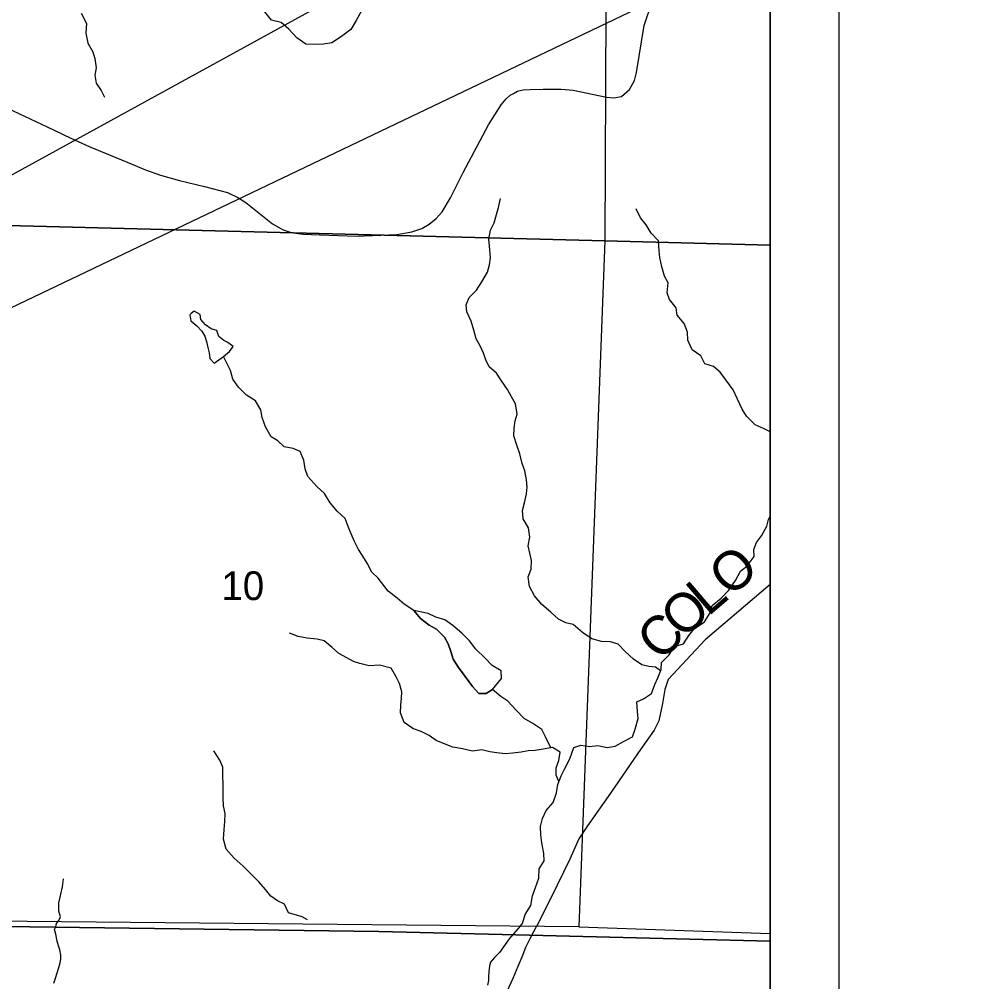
# Model space of a CAD drawing. Extents: x 0 to 34, y 0 to 22.
# Drawn here: x 7.806 to 9.2, y 17.833 to 19.235 of the extents above; entities that cross this region are included whole.
import ezdxf

# ---------------------------------------------------------------- set-up
doc = ezdxf.new("R2010")
doc.units = 0
for name, color, linetype in [('Default', 7, 'Continuous'), ('GM_X_Corporation', 7, 'Continuous'), ('GM_X_County_Road_Text', 7, 'Continuous'), ('GM_X_Interchange_Ramps', 7, 'Continuous'), ('GM_X_Interstate_Route', 7, 'Continuous'), ('GM_X_Major_Lake', 7, 'Continuous'), ('GM_X_Minor_Lake', 7, 'Continuous'), ('GM_X_Minor_River', 7, 'Continuous'), ('GM_X_Township_Road_Text', 7, 'Continuous'), ('SH_Cut_Line', 7, 'Continuous'), ('SH_Data', 7, 'Continuous')]:
    doc.layers.add(name, color=color, linetype=linetype)

msp = doc.modelspace()

# ---------------------------------------------------------------- linework, layer by layer
at = {"layer": 'Default'}
for points in [[(8.9, 18.9055), (8.9, 19.9241), (8.6637, 19.9273), (8.659, 18.9119)], [(8.9, 17.9031), (8.9, 18.9055), (8.659, 18.9119), (8.6215, 17.9129)]]:
    msp.add_lwpolyline(points, close=True, dxfattribs=at)
at = {"layer": 'GM_X_Corporation'}
msp.add_lwpolyline([(8.9, 18.4116), (8.8053, 18.3308), (8.7515, 18.2731), (8.7468, 18.2586), (8.7431, 18.2383), (8.7376, 18.213), (8.7312, 18.1991), (8.7079, 18.166), (8.6673, 18.1074), (8.6339, 18.0598), (8.6215, 18.0409), (8.6083, 18.0114), (8.5807, 17.9546), (8.5594, 17.9133)], dxfattribs=at)
at = {"layer": 'GM_X_Interchange_Ramps'}
for points in [[(8.9, 17.8921), (8.9, 20.9), (6.6698, 20.9), (6.6438, 19.9593), (6.6304, 19.2166), (6.6258, 18.9603), (6.6079, 18.3189), (6.5943, 17.9356), (7.6027, 17.9156), (8.3297, 17.9059), (8.5492, 17.9006)], [(6.5113, 14.1), (8.9, 14.1), (8.9, 17.8921), (8.5492, 17.9006), (8.3297, 17.9059), (7.6027, 17.9156), (6.5943, 17.9356), (6.5883, 17.471), (6.5647, 16.5359), (6.5572, 16.1864), (6.5411, 15.4243), (6.5389, 15.3228)]]:
    msp.add_lwpolyline(points, close=True, dxfattribs=at)
msp.add_lwpolyline([(7.7718, 19.1131), (7.8466, 19.0782), (7.8814, 19.0615), (7.9081, 19.0494), (7.963, 19.0266), (7.99, 19.0156), (8.0118, 19.0077), (8.0396, 18.9999), (8.076, 18.9911), (8.1095, 18.9822), (8.1245, 18.9749), (8.1359, 18.9679), (8.1749, 18.9366), (8.1905, 18.9279), (8.202, 18.924), (8.2199, 18.9219), (8.2441, 18.9208), (8.2976, 18.919), (8.3562, 18.921), (8.3781, 18.925), (8.3926, 18.9297), (8.4034, 18.9364), (8.4134, 18.9446), (8.4223, 18.9542), (8.4341, 18.9745), (8.4529, 19.0115), (8.4897, 19.0808), (8.5081, 19.1101), (8.5154, 19.1188), (8.5212, 19.1242), (8.526, 19.1268), (8.532, 19.1298), (8.54, 19.1321), (8.5506, 19.1326), (8.5694, 19.1328), (8.5954, 19.1331), (8.613, 19.1312), (8.6615, 19.1212), (8.6722, 19.1202), (8.6833, 19.1223), (8.6949, 19.1325), (8.7025, 19.1454), (8.7051, 19.157), (8.7167, 19.2254), (8.7288, 19.2617)], dxfattribs=at)
at = {"layer": 'GM_X_Interstate_Route'}
msp.add_lwpolyline([(8.517, 17.8189), (8.5254, 17.8382), (8.5331, 17.8557), (8.5385, 17.8692), (8.5442, 17.883), (8.5503, 17.8957), (8.5556, 17.9062), (8.5594, 17.9133)], dxfattribs=at)
at = {"layer": 'GM_X_Minor_Lake'}
for points in [[(7.6626, 19.9442), (8.6637, 19.9273), (8.659, 18.9119), (7.637, 18.9382)], [(7.637, 18.9382), (8.659, 18.9119), (8.6215, 17.9129), (7.6162, 17.9223)]]:
    msp.add_lwpolyline(points, close=True, dxfattribs=at)
at = {"layer": 'GM_X_Minor_River'}
for points in [[(8.0567, 18.8063), (8.0543, 18.8044), (8.0562, 18.7956), (8.0646, 18.7881), (8.0719, 18.7806), (8.0765, 18.773), (8.0789, 18.7651), (8.0809, 18.7567), (8.0828, 18.7488), (8.0836, 18.7404), (8.0898, 18.734), (8.1034, 18.7437)], [(8.1034, 18.7437), (8.1121, 18.7509), (8.1177, 18.7582), (8.1097, 18.7638), (8.1039, 18.7668), (8.0967, 18.7728), (8.0939, 18.7815), (8.0856, 18.7837), (8.0775, 18.7898), (8.0706, 18.7973), (8.0694, 18.8049), (8.0607, 18.8093), (8.0567, 18.8063)], [(8.3811, 18.3733), (8.3907, 18.362), (8.4034, 18.3524), (8.4137, 18.3461), (8.4257, 18.3346), (8.4307, 18.3248), (8.4347, 18.3138), (8.4383, 18.3025), (8.4461, 18.2905), (8.4557, 18.2774), (8.4662, 18.2628), (8.4758, 18.2527), (8.4864, 18.2525), (8.4955, 18.2583)], [(8.4955, 18.2583), (8.5088, 18.2745), (8.5082, 18.2855), (8.4952, 18.2936), (8.4841, 18.3048), (8.4714, 18.3171), (8.4621, 18.3295), (8.4509, 18.3403), (8.4375, 18.3518), (8.426, 18.36), (8.413, 18.3639), (8.4016, 18.3691), (8.3811, 18.3733)]]:
    msp.add_lwpolyline(points, dxfattribs=at)
at = {"layer": 'GM_X_Township_Road_Text'}
for points in [[(8.3164, 19.2599), (8.3046, 19.2469), (8.2968, 19.2331), (8.2889, 19.2198), (8.2757, 19.2094), (8.2613, 19.2002), (8.2492, 19.1982), (8.2367, 19.1977), (8.2234, 19.1983), (8.2104, 19.2077), (8.1989, 19.2201), (8.1878, 19.2299), (8.1733, 19.2332), (8.1637, 19.2453), (8.1545, 19.2573), (8.1487, 19.2725), (8.1474, 19.2857), (8.1431, 19.2993), (8.1339, 19.3107)], [(7.8963, 19.2437), (7.9041, 19.2286), (7.903, 19.2142), (7.9058, 19.1998), (7.9131, 19.1873), (7.9163, 19.1775), (7.9179, 19.1638), (7.9161, 19.1535), (7.9181, 19.1414), (7.9254, 19.1309), (7.93, 19.121)], [(8.7404, 18.2858), (8.733, 18.2912), (8.7235, 18.2918), (8.7132, 18.2943), (8.701, 18.3025), (8.6887, 18.3136), (8.6787, 18.3245), (8.6673, 18.3281), (8.6544, 18.3282), (8.6403, 18.3322), (8.6265, 18.3414), (8.6131, 18.3533), (8.6025, 18.3554), (8.5918, 18.3609), (8.5806, 18.371), (8.5672, 18.3821), (8.5568, 18.3949), (8.5493, 18.4084), (8.5476, 18.4224), (8.5519, 18.4339), (8.5525, 18.4464), (8.5476, 18.4676), (8.5497, 18.4805), (8.5479, 18.4938), (8.5401, 18.5069), (8.5392, 18.519), (8.542, 18.5305), (8.5448, 18.5434), (8.5462, 18.5533), (8.5452, 18.5639), (8.5424, 18.5768), (8.5388, 18.5877), (8.5355, 18.6017), (8.5308, 18.6141), (8.5268, 18.6277), (8.527, 18.6391), (8.5287, 18.6498), (8.5315, 18.6593), (8.529, 18.6744), (8.5232, 18.6846), (8.5173, 18.6955), (8.5084, 18.7079), (8.5014, 18.7191), (8.4906, 18.7284), (8.4859, 18.7386), (8.4824, 18.7484), (8.4773, 18.7589), (8.4718, 18.7691), (8.4682, 18.7819), (8.4642, 18.7951), (8.4579, 18.8087), (8.457, 18.8189), (8.4617, 18.8292), (8.4721, 18.84), (8.4802, 18.8523), (8.4883, 18.8661), (8.4912, 18.8768), (8.4925, 18.8878), (8.4911, 18.9041), (8.4902, 18.9143), (8.4926, 18.9273), (8.4981, 18.938), (8.5013, 18.9502), (8.5042, 18.9605), (8.507, 18.9734)], [(8.9, 18.634), (8.8911, 18.6381), (8.8781, 18.644), (8.8658, 18.6567), (8.8592, 18.6668), (8.8525, 18.6811), (8.8462, 18.695), (8.8354, 18.7093), (8.8273, 18.7209), (8.8177, 18.7291), (8.8051, 18.733), (8.7989, 18.7447), (8.7862, 18.7532), (8.7799, 18.7671), (8.7794, 18.7789), (8.7746, 18.7917), (8.7646, 18.8037), (8.7629, 18.8143), (8.7532, 18.8266), (8.75, 18.8364), (8.7513, 18.8509), (8.7462, 18.8607), (8.7422, 18.8742), (8.7393, 18.8875), (8.7384, 18.8973), (8.7374, 18.9121), (8.7266, 18.9229), (8.7192, 18.9353), (8.7111, 18.9454), (8.7048, 18.9586)], [(8.3289, 18.4205), (8.3198, 18.4296), (8.3129, 18.4424), (8.3067, 18.4526), (8.3002, 18.4624), (8.294, 18.4749), (8.2897, 18.4851), (8.2851, 18.4957), (8.2808, 18.5075), (8.2693, 18.5184), (8.259, 18.5304), (8.2509, 18.5437), (8.2398, 18.5542), (8.2264, 18.5689), (8.2225, 18.5799), (8.2208, 18.5924), (8.2154, 18.6053), (8.2051, 18.6097), (8.1922, 18.6119), (8.1826, 18.6205), (8.1731, 18.6265), (8.1646, 18.6409), (8.1599, 18.6545), (8.158, 18.6659), (8.1502, 18.6791), (8.1369, 18.6874), (8.1254, 18.699), (8.1173, 18.7107), (8.1138, 18.7229), (8.1034, 18.7437)], [(8.5358, 17.9136), (8.539, 17.9176), (8.5429, 17.9309), (8.5514, 17.944), (8.5538, 17.958), (8.5581, 17.9703), (8.5632, 17.9836), (8.5637, 17.9973), (8.5707, 18.0088), (8.5702, 18.0194), (8.5676, 18.0353), (8.5659, 18.0467), (8.5654, 18.0588), (8.5682, 18.0706), (8.5737, 18.0821), (8.5841, 18.094), (8.5888, 18.1078), (8.5908, 18.1203), (8.5955, 18.1329), (8.6003, 18.1425), (8.6084, 18.1574), (8.6138, 18.1738), (8.624, 18.1774), (8.6369, 18.1754), (8.6489, 18.1767), (8.6626, 18.1739), (8.6743, 18.176), (8.6871, 18.1834), (8.6995, 18.1897), (8.7034, 18.2008), (8.7077, 18.2164), (8.7068, 18.2263), (8.7058, 18.2403), (8.7156, 18.245), (8.7272, 18.2524), (8.7319, 18.2658), (8.7366, 18.2754), (8.741, 18.2876), (8.7419, 18.2979), (8.7531, 18.309), (8.7605, 18.3209), (8.7737, 18.325), (8.7814, 18.3372), (8.7892, 18.3469), (8.8046, 18.357), (8.8127, 18.37), (8.8155, 18.3807), (8.8286, 18.3915), (8.8397, 18.4031), (8.8494, 18.4173), (8.8567, 18.4307), (8.8664, 18.4385), (8.8768, 18.4523), (8.8762, 18.4622), (8.8802, 18.4725), (8.8873, 18.4825), (8.8954, 18.4963), (8.8978, 18.5062), (8.9, 18.5109)], [(8.5804, 18.1736), (8.5727, 18.1894), (8.5672, 18.2), (8.5542, 18.2089), (8.5415, 18.2162), (8.53, 18.2282), (8.5177, 18.2416), (8.5077, 18.2483), (8.4955, 18.2583), (8.4864, 18.2525), (8.4758, 18.2527), (8.4662, 18.2628), (8.4557, 18.2774), (8.4461, 18.2905), (8.4383, 18.3025), (8.4347, 18.3138), (8.4307, 18.3248), (8.4257, 18.3346), (8.4137, 18.3461), (8.4034, 18.3524), (8.3907, 18.362), (8.3811, 18.3733), (8.3666, 18.3829), (8.3566, 18.3914), (8.3435, 18.4015), (8.3289, 18.4205)], [(8.3308, 18.2941), (8.316, 18.2928), (8.3023, 18.2961), (8.2928, 18.2991), (8.2832, 18.3047), (8.2718, 18.311), (8.2618, 18.3197), (8.2503, 18.3295), (8.2401, 18.332), (8.2256, 18.3331), (8.2123, 18.3356), (8.1997, 18.3404)], [(8.5923, 18.1243), (8.5883, 18.1339), (8.5882, 18.1446), (8.5922, 18.1549), (8.5942, 18.1671), (8.5828, 18.1741), (8.5695, 18.1716), (8.5575, 18.1698), (8.5473, 18.1689), (8.5374, 18.1672), (8.525, 18.1659), (8.514, 18.1649), (8.5019, 18.1662), (8.4916, 18.1676), (8.4802, 18.1704), (8.4666, 18.1687), (8.4518, 18.1722), (8.4378, 18.1746), (8.4267, 18.179), (8.4134, 18.1841), (8.4034, 18.1915), (8.3924, 18.197), (8.3794, 18.2017), (8.3668, 18.2106), (8.3616, 18.2245), (8.3618, 18.2355), (8.3628, 18.2458), (8.3634, 18.2553), (8.3602, 18.267), (8.3551, 18.2768), (8.348, 18.2896), (8.3308, 18.2941)], [(8.2258, 17.9228), (8.2183, 17.9271), (8.1985, 17.9333), (8.1923, 17.9458), (8.1824, 17.9507), (8.1725, 17.9574), (8.1648, 17.9672), (8.1552, 17.9785), (8.1323, 18.0011), (8.1189, 18.0128), (8.1074, 18.0259), (8.1034, 18.0403), (8.1048, 18.0544), (8.1055, 18.0662), (8.1058, 18.078), (8.1038, 18.089), (8.103, 18.1), (8.1029, 18.1117), (8.1032, 18.1216), (8.1027, 18.1322), (8.1026, 18.1455), (8.0983, 18.1557), (8.0895, 18.169)], [(7.8661, 17.9273), (7.8639, 17.9354), (7.8638, 17.9475), (7.8667, 17.9605), (7.8689, 17.9711), (7.8703, 17.9829)], [(7.8564, 17.8307), (7.8589, 17.838), (7.8614, 17.846), (7.8636, 17.8537), (7.8654, 17.8605), (7.8665, 17.8659), (7.8668, 17.8716), (7.8651, 17.8792), (7.8632, 17.8849), (7.8612, 17.8921), (7.8591, 17.902), (7.8575, 17.9088), (7.8592, 17.9129), (7.8601, 17.9174), (7.8635, 17.9221), (7.8661, 17.9273)], [(8.5358, 17.9136), (8.5199, 17.8954), (8.5058, 17.8755), (8.4985, 17.8679), (8.4924, 17.8615), (8.4913, 17.8558), (8.4901, 17.8474), (8.4897, 17.8405), (8.4896, 17.8345), (8.4881, 17.828)]]:
    msp.add_lwpolyline(points, dxfattribs=at)
at = {"layer": 'SH_Cut_Line'}
for points in [[(8.9, 17.8921), (8.9, 20.9), (2.1, 20.9), (2.1, 17.9098), (2.4376, 17.9025), (2.6711, 17.8975), (2.9484, 17.8857), (3.604, 17.8577), (3.7063, 17.8588), (3.7128, 17.9822), (4.1825, 17.9744), (4.4481, 17.9728), (4.5919, 17.9719), (4.9267, 17.9702), (4.9368, 17.9702), (4.994, 17.969), (5.3871, 17.9608), (5.6339, 17.9555), (6.0729, 17.9463), (6.24, 17.9427), (6.5943, 17.9356), (7.6027, 17.9156), (8.3297, 17.9059), (8.5492, 17.9006)], [(2.1, 17.9098), (2.1, 14.1), (8.9, 14.1), (8.9, 17.8921), (8.5492, 17.9006), (8.3297, 17.9059), (7.6027, 17.9156), (6.5943, 17.9356), (6.24, 17.9427), (6.0729, 17.9463), (5.6339, 17.9555), (5.3871, 17.9608), (4.994, 17.969), (4.9368, 17.9702), (4.9267, 17.9702), (4.5919, 17.9719), (4.4481, 17.9728), (4.1825, 17.9744), (3.7128, 17.9822), (3.7063, 17.8588), (3.604, 17.8577), (2.9484, 17.8857), (2.6711, 17.8975), (2.4376, 17.9025)]]:
    msp.add_lwpolyline(points, close=True, dxfattribs=at)
at = {"layer": 'SH_Data'}
for p, q in [((9, 21), (9, 14)), ((8.9, 20.9), (8.9, 14.1))]:
    msp.add_line(p, q, dxfattribs=at)
msp.add_lwpolyline([(9.2998, 19.834), (5.078, 17.5171), (9.2998, 19.5346)], close=True, dxfattribs=at)

# ---------------------------------------------------------------- texts
at = {"layer": 'GM_X_County_Road_Text'}
msp.add_text('10', height=0.04186, rotation=0, dxfattribs=at).set_placement((8.1006, 18.3887))
at = {"layer": 'GM_X_Major_Lake'}
for s, rotation, p in [('O', 40.6288, (8.8418, 18.3915)), ('L', 40.5787, (8.8095, 18.3639)), ('O', 42.8564, (8.7733, 18.3303)), ('C', 45.2111, (8.7409, 18.2976))]:
    msp.add_text(s, height=0.0568, rotation=rotation, dxfattribs=at).set_placement(p)

doc.saveas('drawing.dxf')
